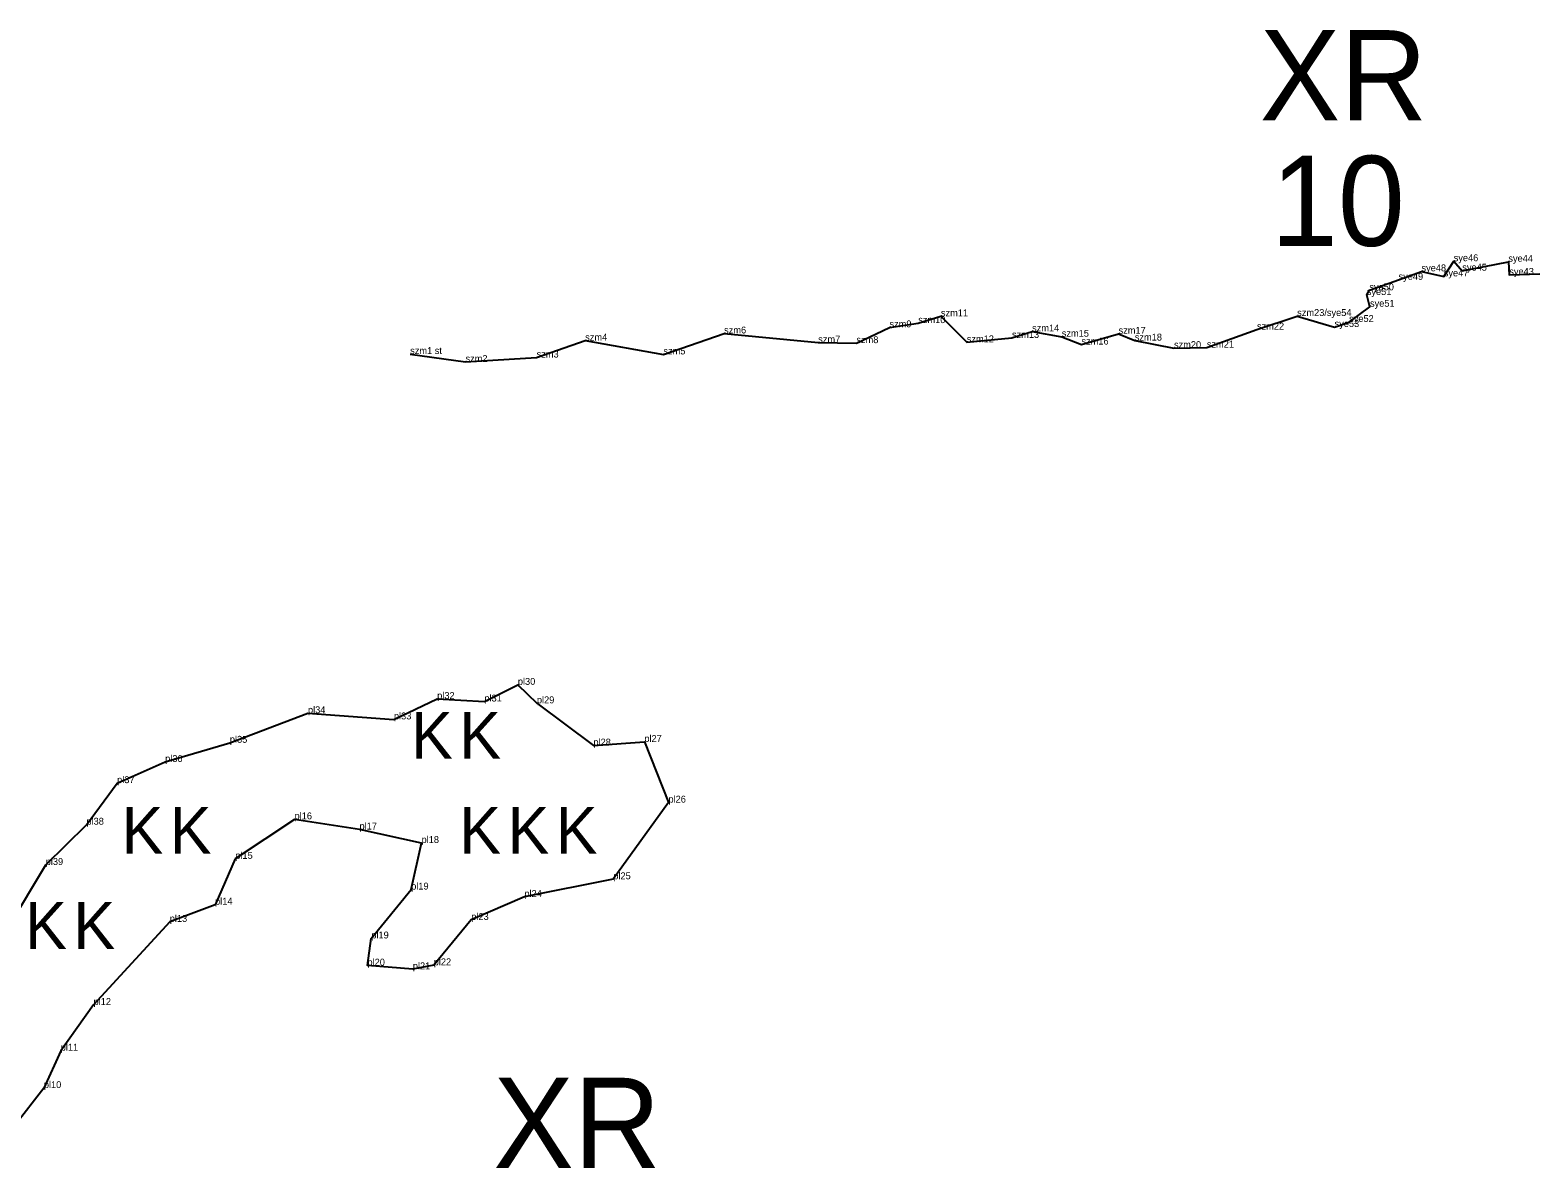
# Model space of a CAD drawing. Extents: x 2072529 to 2268812, y 436423 to 470008.
# Drawn here: x 2234269 to 2235363, y 438101 to 438927 of the extents above; entities that cross this region are included whole.
import ezdxf

# ---------------------------------------------------------------- set-up
doc = ezdxf.new("R2010")
doc.units = 0
for name, color, linetype in [('Old_Level_10', 7, 'Continuous'), ('Old_Level_20', 7, 'Continuous'), ('Old_Level_52', 7, 'Continuous'), ('Old_Level_55', 7, 'Continuous'), ('Old_Level_60', 7, 'Continuous'), ('Old_Level_62', 7, 'Continuous')]:
    doc.layers.add(name, color=color, linetype=linetype)

msp = doc.modelspace()

# ---------------------------------------------------------------- linework, layer by layer
at = {"layer": 'Old_Level_10'}
msp.add_lwpolyline([(2234544.932, 438691.786), (2234585.06, 438686.09), (2234636.668, 438689.26), (2234671.902, 438701.54), (2234728.631, 438691.521), (2234772.688, 438706.717), (2234840.96, 438700.074), (2234868.634, 438699.711), (2234892.634, 438711.167), (2234913.531, 438714.207), (2234929.97, 438719.163), (2234948.724, 438700.303), (2234981.506, 438703.5), (2234996.091, 438708.194), (2235017.648, 438704.352), (2235031.904, 438698.687), (2235058.858, 438706.496), (2235070.622, 438701.588), (2235099.05, 438696.134), (2235122.875, 438696.452), (2235159.252, 438709.525), (2235188.417, 438719.372), (2235215.563, 438711.408), (2235226.114, 438715.036), (2235241.244, 438726.087), (2235238.894, 438734.628), (2235240.774, 438738.014), (2235261.97, 438745.641), (2235278.603, 438751.775), (2235294.772, 438748.125), (2235301.96, 438759.131), (2235308.21, 438752.259), (2235341.617, 438758.721), (2235342.273, 438749.255), (2235364.405, 438750.026)], dxfattribs=at)
at = {"layer": 'Old_Level_20'}
for p, q in [((2235301.96, 438759.131), (2235301.96, 438759.131)), ((2235341.617, 438758.721), (2235341.617, 438758.721)), ((2235261.97, 438745.641), (2235261.97, 438745.641)), ((2235278.603, 438751.775), (2235278.603, 438751.775)), ((2235294.772, 438748.125), (2235294.772, 438748.125)), ((2235308.21, 438752.259), (2235308.21, 438752.259)), ((2235342.273, 438749.255), (2235342.273, 438749.255)), ((2235238.894, 438734.628), (2235238.894, 438734.628)), ((2235240.774, 438738.014), (2235240.774, 438738.014)), ((2235241.244, 438726.087), (2235241.244, 438726.087)), ((2234892.634, 438711.167), (2234892.634, 438711.167)), ((2234913.531, 438714.207), (2234913.531, 438714.207)), ((2234929.97, 438719.163), (2234929.97, 438719.163)), ((2235159.252, 438709.525), (2235159.252, 438709.525)), ((2235188.417, 438719.372), (2235188.417, 438719.372)), ((2235215.563, 438711.408), (2235215.563, 438711.408)), ((2235226.114, 438715.036), (2235226.114, 438715.036)), ((2234671.902, 438701.54), (2234671.902, 438701.54)), ((2234772.688, 438706.717), (2234772.688, 438706.717)), ((2234840.96, 438700.074), (2234840.96, 438700.074)), ((2234868.634, 438699.711), (2234868.634, 438699.711)), ((2234948.724, 438700.303), (2234948.724, 438700.303)), ((2234981.506, 438703.5), (2234981.506, 438703.5)), ((2234996.091, 438708.194), (2234996.091, 438708.194)), ((2235017.648, 438704.352), (2235017.648, 438704.352)), ((2235031.904, 438698.687), (2235031.904, 438698.687)), ((2235058.858, 438706.496), (2235058.858, 438706.496)), ((2235070.622, 438701.588), (2235070.622, 438701.588)), ((2234544.932, 438691.786), (2234544.932, 438691.786)), ((2234636.668, 438689.26), (2234636.668, 438689.26)), ((2234728.631, 438691.521), (2234728.631, 438691.521)), ((2235099.05, 438696.134), (2235099.05, 438696.134)), ((2235122.875, 438696.452), (2235122.875, 438696.452)), ((2234585.06, 438686.09), (2234585.06, 438686.09)), ((2234623.048, 438451.84), (2234623.048, 438451.84)), ((2234564.523, 438441.602), (2234564.523, 438441.602)), ((2234598.775, 438439.749), (2234598.775, 438439.749)), ((2234636.866, 438438.428), (2234636.866, 438438.428)), ((2234470.8, 438431.253), (2234470.8, 438431.253)), ((2234533.157, 438426.75), (2234533.157, 438426.75)), ((2234414.129, 438409.811), (2234414.129, 438409.811)), ((2234677.886, 438407.809), (2234677.886, 438407.809)), ((2234714.811, 438410.399), (2234714.811, 438410.399)), ((2234367.187, 438395.873), (2234367.187, 438395.873)), ((2234332.323, 438380.53), (2234332.323, 438380.53)), ((2234732.303, 438366.408), (2234732.303, 438366.408)), ((2234310.076, 438350.382), (2234310.076, 438350.382)), ((2234461.065, 438354.265), (2234461.065, 438354.265)), ((2234508.187, 438346.889), (2234508.187, 438346.889)), ((2234553.208, 438337.093), (2234553.208, 438337.093)), ((2234280.543, 438321.152), (2234280.543, 438321.152)), ((2234418.048, 438325.586), (2234418.048, 438325.586)), ((2234692.291, 438310.78), (2234692.291, 438310.78)), ((2234545.673, 438303.323), (2234545.673, 438303.323)), ((2234627.789, 438297.954), (2234627.789, 438297.954)), ((2234403.377, 438292.335), (2234403.377, 438292.335)), ((2234370.518, 438279.896), (2234370.518, 438279.896)), ((2234589.26, 438281.28), (2234589.26, 438281.28)), ((2234516.736, 438267.861), (2234516.736, 438267.861)), ((2234513.957, 438248.14), (2234513.957, 438248.14)), ((2234546.857, 438245.479), (2234546.857, 438245.479)), ((2234562.027, 438248.401), (2234562.027, 438248.401)), ((2234315.232, 438219.626), (2234315.232, 438219.626)), ((2234291.416, 438186.429), (2234291.416, 438186.429)), ((2234279.174, 438159.319), (2234279.174, 438159.319))]:
    msp.add_line(p, q, dxfattribs=at)
at = {"layer": 'Old_Level_52'}
msp.add_lwpolyline([(2234253.57, 438275.929), (2234280.543, 438321.152), (2234310.076, 438350.382), (2234332.323, 438380.53), (2234367.187, 438395.873), (2234414.129, 438409.811), (2234470.8, 438431.253), (2234533.157, 438426.75), (2234564.523, 438441.602), (2234598.775, 438439.749), (2234623.048, 438451.84), (2234636.866, 438438.428), (2234677.886, 438407.809), (2234714.811, 438410.399), (2234732.303, 438366.408), (2234692.291, 438310.78), (2234627.789, 438297.954), (2234589.26, 438281.28), (2234562.027, 438248.401), (2234546.857, 438245.479), (2234513.957, 438248.14), (2234516.736, 438267.861), (2234545.673, 438303.323), (2234553.208, 438337.093), (2234508.187, 438346.889), (2234461.065, 438354.265), (2234418.048, 438325.586), (2234403.377, 438292.335), (2234370.518, 438279.896), (2234315.232, 438219.626), (2234291.416, 438186.429), (2234279.174, 438159.319), (2234258.17, 438132.282)], dxfattribs=at)

# ---------------------------------------------------------------- texts
at = {"layer": 'Old_Level_55'}
for p in [(2234545.577, 438398.244), (2234580.577, 438398.244), (2234335.577, 438329.244), (2234370.577, 438329.244), (2234580.577, 438329.244), (2234615.577, 438329.244), (2234650.577, 438329.244), (2234265.577, 438260.244), (2234300.577, 438260.244)]:
    msp.add_text('K', height=34, dxfattribs=at).set_placement(p)
at = {"layer": 'Old_Level_60'}
for s, p in [('sye46', (2235301.96, 438759.131)), ('sye48', (2235278.603, 438751.775)), ('sye47', (2235294.772, 438748.125)), ('sye45', (2235308.21, 438752.259)), ('sye44', (2235341.617, 438758.721)), ('sye43', (2235342.273, 438749.255)), ('sye50', (2235240.774, 438738.014)), ('sye49', (2235261.97, 438745.641)), ('sye51', (2235238.894, 438734.628)), ('szm11', (2234929.97, 438719.163)), ('szm23/sye54', (2235188.417, 438719.372)), ('sye51', (2235241.244, 438726.087)), ('szm6', (2234772.688, 438706.717)), ('szm9', (2234892.634, 438711.167)), ('szm10', (2234913.531, 438714.207)), ('szm14', (2234996.091, 438708.194)), ('szm15', (2235017.648, 438704.352)), ('szm17', (2235058.858, 438706.496)), ('szm22', (2235159.252, 438709.525)), ('sye53', (2235215.563, 438711.408)), ('sye52', (2235226.114, 438715.036)), ('szm4', (2234671.902, 438701.54)), ('szm7', (2234840.96, 438700.074)), ('szm8', (2234868.634, 438699.711)), ('szm12', (2234948.724, 438700.303)), ('szm13', (2234981.506, 438703.5)), ('szm16', (2235031.904, 438698.687)), ('szm18', (2235070.622, 438701.588)), ('szm20', (2235099.05, 438696.134)), ('szm21', (2235122.875, 438696.452)), ('szm1 st', (2234544.932, 438691.786)), ('szm2', (2234585.06, 438686.09)), ('szm3', (2234636.668, 438689.26)), ('szm5', (2234728.631, 438691.521)), ('pl32', (2234564.523, 438441.602)), ('pl30', (2234623.048, 438451.84)), ('pl34', (2234470.8, 438431.253)), ('pl31', (2234598.775, 438439.749)), ('pl29', (2234636.866, 438438.428)), ('pl33', (2234533.157, 438426.75)), ('pl35', (2234414.129, 438409.811)), ('pl27', (2234714.811, 438410.399)), ('pl28', (2234677.886, 438407.809)), ('pl36', (2234367.187, 438395.873)), ('pl37', (2234332.323, 438380.53)), ('pl26', (2234732.303, 438366.408)), ('pl16', (2234461.065, 438354.265)), ('pl38', (2234310.076, 438350.382)), ('pl17', (2234508.187, 438346.889)), ('pl18', (2234553.208, 438337.093)), ('pl15', (2234418.048, 438325.586)), ('pl39', (2234280.543, 438321.152)), ('pl25', (2234692.291, 438310.78)), ('pl19', (2234545.673, 438303.323)), ('pl14', (2234403.377, 438292.335)), ('pl24', (2234627.789, 438297.954)), ('pl13', (2234370.518, 438279.896)), ('pl23', (2234589.26, 438281.28)), ('pl19', (2234516.736, 438267.861)), ('pl20', (2234513.957, 438248.14)), ('pl21', (2234546.857, 438245.479)), ('pl22', (2234562.027, 438248.401)), ('pl12', (2234315.232, 438219.626)), ('pl11', (2234291.416, 438186.429)), ('pl10', (2234279.174, 438159.319))]:
    msp.add_text(s, height=5, dxfattribs=at).set_placement(p)
at = {"layer": 'Old_Level_62'}
for s, p in [('XR', (2235161.316, 438861.406)), ('10', (2235169.364, 438770.258)), ('XR', (2234605.281, 438101.455))]:
    msp.add_text(s, height=65.34, dxfattribs=at).set_placement(p)

doc.saveas('drawing.dxf')
